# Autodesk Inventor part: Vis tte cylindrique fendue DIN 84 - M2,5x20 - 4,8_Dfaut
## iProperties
Created: 2007-07
Part Number: Vis tte cylindrique fendue DIN 84 - M2,5x20 - 4,8_Dfaut
Document SubType Name: Modeling
Designer: EF
Density: 1 g/cm^3
Author: EF
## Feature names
1. Base1
